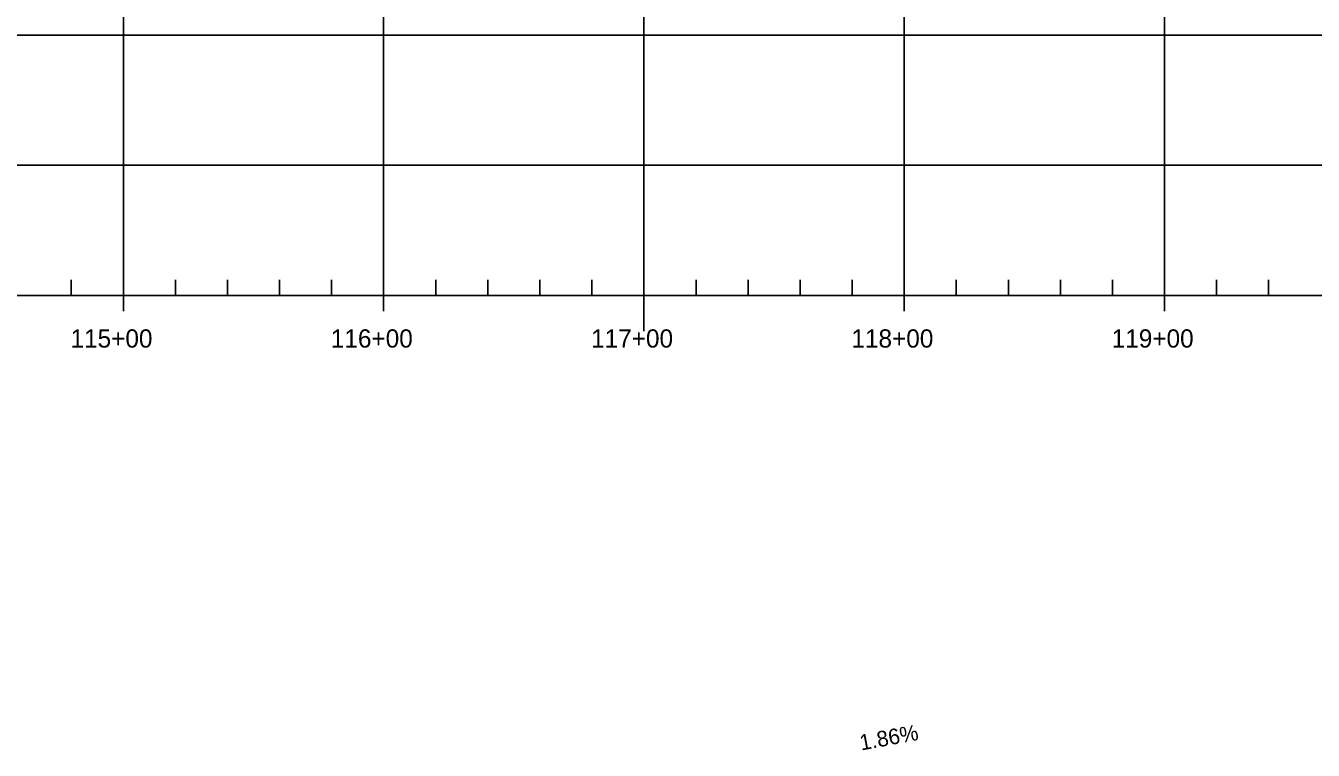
# Model space of a CAD drawing. Extents: x 688474 to 694748, y 765018 to 767373.
# Drawn here: x 692416.1 to 692910.7, y 765635.3 to 765913.5 of the extents above; entities that cross this region are included whole.
import ezdxf

# ---------------------------------------------------------------- set-up
doc = ezdxf.new("R2010")
doc.units = 0
for name, color, linetype in [('30', 7, 'Continuous'), ('37', 7, 'Continuous'), ('R_No Plot', 7, 'Continuous'), ('R_Vert Alg Annot', 7, 'Continuous')]:
    doc.layers.add(name, color=color, linetype=linetype)

msp = doc.modelspace()

# ---------------------------------------------------------------- linework, layer by layer
at = {"layer": '37'}
for p, q in [((692453.59, 765809.92), (692453.59, 766359.92)), ((692553.59, 765809.92), (692553.59, 766359.92)), ((692653.59, 765809.92), (692653.59, 766359.92)), ((692753.59, 765809.92), (692753.59, 766359.92)), ((692853.59, 765809.92), (692853.59, 766359.92)), ((690853.59, 765909.92), (693453.59, 765909.92)), ((690853.59, 765859.92), (693453.59, 765859.92)), ((692433.59, 765809.92), (692433.59, 765815.92)), ((692473.59, 765809.92), (692473.59, 765815.92)), ((692493.59, 765809.92), (692493.59, 765815.92)), ((692513.59, 765809.92), (692513.59, 765815.92)), ((692533.59, 765809.92), (692533.59, 765815.92)), ((692573.59, 765809.92), (692573.59, 765815.92)), ((692593.59, 765809.92), (692593.59, 765815.92)), ((692613.59, 765809.92), (692613.59, 765815.92)), ((692633.59, 765809.92), (692633.59, 765815.92)), ((692673.59, 765809.92), (692673.59, 765815.92)), ((692693.59, 765809.92), (692693.59, 765815.92)), ((692713.59, 765809.92), (692713.59, 765815.92)), ((692733.59, 765809.92), (692733.59, 765815.92)), ((692773.59, 765809.92), (692773.59, 765815.92)), ((692793.59, 765809.92), (692793.59, 765815.92)), ((692813.59, 765809.92), (692813.59, 765815.92)), ((692833.59, 765809.92), (692833.59, 765815.92)), ((692873.59, 765809.92), (692873.59, 765815.92)), ((692893.59, 765809.92), (692893.59, 765815.92)), ((690853.59, 765809.92), (693453.59, 765809.92)), ((692453.59, 765803.92), (692453.59, 765809.92)), ((692553.59, 765803.92), (692553.59, 765809.92)), ((692653.59, 765803.92), (692653.59, 765809.92)), ((692753.59, 765803.92), (692753.59, 765809.92)), ((692853.59, 765803.92), (692853.59, 765809.92))]:
    msp.add_line(p, q, dxfattribs=at)
at = {"layer": 'R_No Plot'}
msp.add_line((692653.59, 766099.88), (692653.59, 765796.18), dxfattribs=at)

# ---------------------------------------------------------------- texts
at = {"layer": '30'}
for s, p in [('115+00', (692433.28, 765789.92)), ('116+00', (692533.28, 765789.92)), ('117+00', (692633.28, 765789.92)), ('118+00', (692733.28, 765789.92)), ('119+00', (692833.28, 765789.92))]:
    msp.add_text(s, height=7, dxfattribs=at).set_placement(p)
at = {"layer": 'R_Vert Alg Annot'}
msp.add_text('1.86%', height=6, rotation=10.5301, dxfattribs=at).set_placement((692737.05, 765635.16))

doc.saveas('drawing.dxf')
